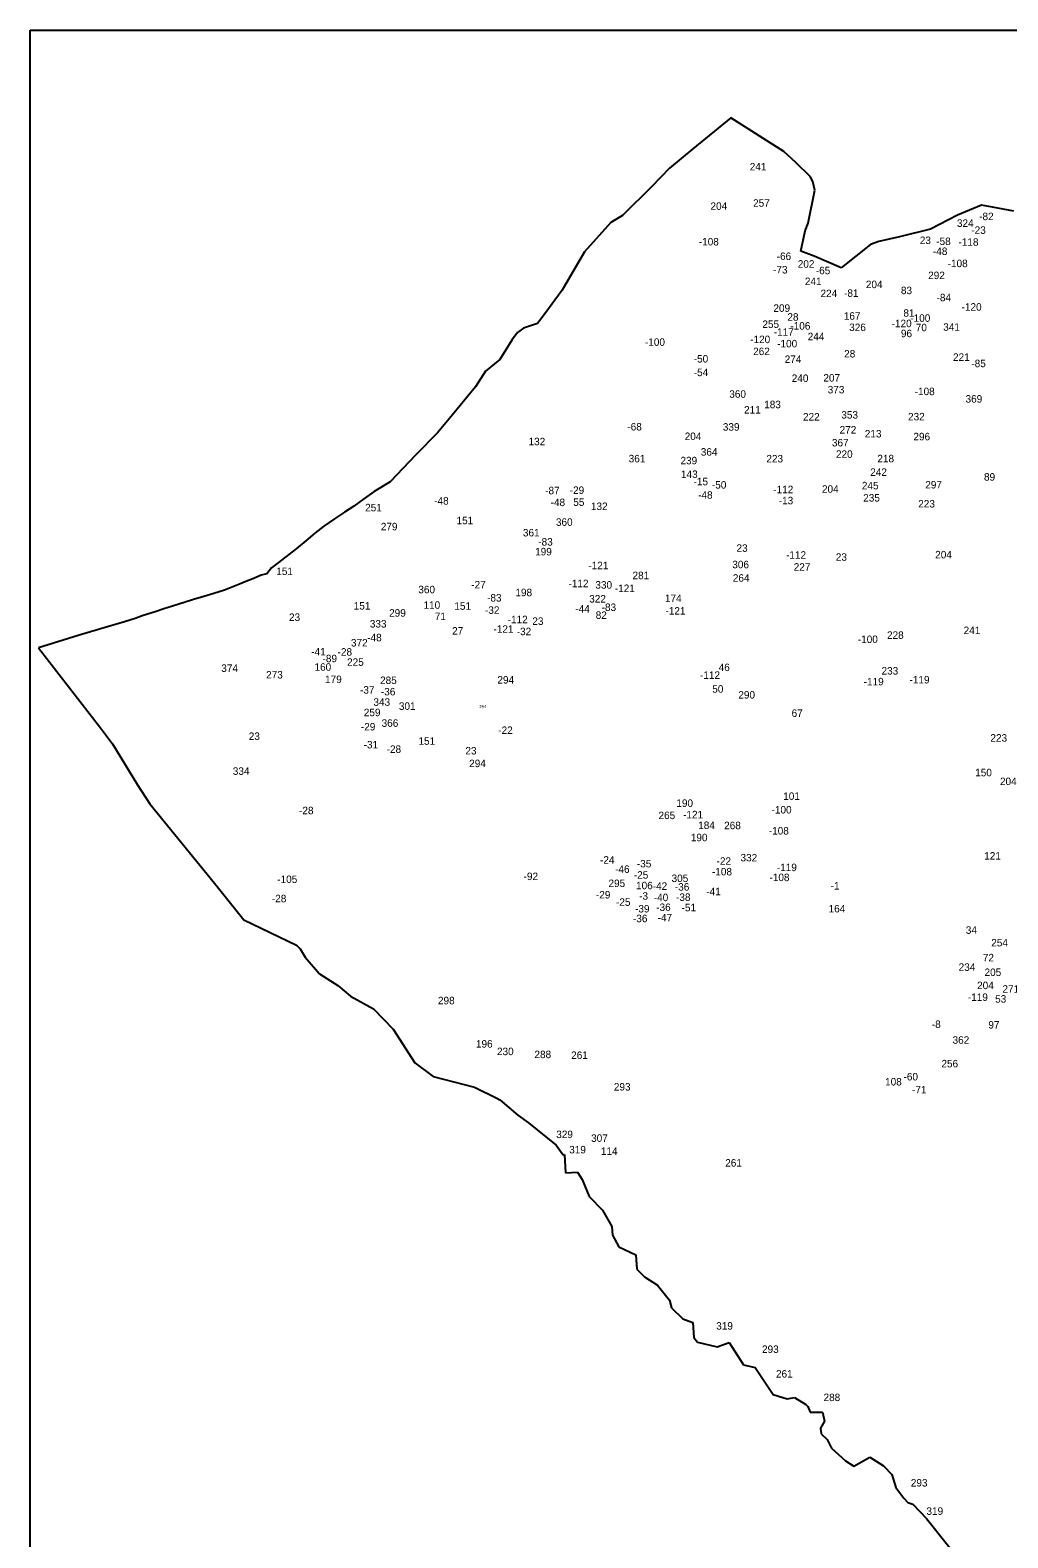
# Model space of a CAD drawing. Extents: x -780246 to -774760, y -968897 to -964868.
# Drawn here: x -780246 to -778940, y -966883 to -964868 of the extents above; entities that cross this region are included whole.
import ezdxf

# ---------------------------------------------------------------- set-up
doc = ezdxf.new("R2010")
doc.units = 0
for name, color, linetype in [('Vrstva 13', 7, 'Continuous'), ('Vrstva 15', 7, 'Continuous'), ('Vrstva 24', 7, 'Continuous')]:
    doc.layers.add(name, color=color, linetype=linetype)

msp = doc.modelspace()

# ---------------------------------------------------------------- linework, layer by layer
at = {"layer": 'Vrstva 13'}
for p, q in [((-779309.6, -964984.69), (-779360.72, -965026.33)), ((-779239.06, -965029.98), (-779309.6, -964984.69)), ((-779360.72, -965026.33), (-779391.82, -965051.9)), ((-779222.92, -965044.3), (-779239.06, -965029.98)), ((-779391.82, -965051.9), (-779415.48, -965076.37)), ((-779203.71, -965063.3), (-779222.92, -965044.3)), ((-779415.48, -965076.37), (-779454.7, -965115.52)), ((-779206.64, -965125.39), (-779197.51, -965081.63)), ((-779200.14, -965070.09), (-779203.71, -965063.3)), ((-779197.51, -965081.63), (-779200.14, -965070.09)), ((-778974.74, -965101.59), (-779006.8, -965114.81)), ((-778959.99, -965104.36), (-778974.74, -965101.59)), ((-779454.7, -965115.52), (-779470.03, -965124.73)), ((-779006.8, -965114.81), (-779042.87, -965133.8)), ((-778931.37, -965109.54), (-778959.99, -965104.36)), ((-779470.03, -965124.73), (-779505.59, -965163.81)), ((-779216.42, -965163.23), (-779210.44, -965135.91)), ((-779210.44, -965135.91), (-779206.64, -965125.39)), ((-779042.87, -965133.8), (-779084.41, -965143.66)), ((-779198.47, -965169.53), (-779216.42, -965163.23)), ((-779122.93, -965154.3), (-779162.25, -965185.45)), ((-779112.09, -965149.94), (-779122.93, -965154.3)), ((-779084.41, -965143.66), (-779112.09, -965149.94)), ((-779505.59, -965163.81), (-779535.39, -965215.38)), ((-779162.25, -965185.45), (-779198.47, -965169.53)), ((-779535.39, -965215.38), (-779558.32, -965246.72)), ((-779568.25, -965259.94), (-779586.8, -965266)), ((-779558.32, -965246.72), (-779568.25, -965259.94)), ((-779602.32, -965281.91), (-779618.53, -965307.85)), ((-779594.95, -965271.61), (-779602.32, -965281.91)), ((-779586.8, -965266), (-779594.95, -965271.61)), ((-779637.81, -965323.55), (-779651.1, -965344.66)), ((-779618.53, -965307.85), (-779637.81, -965323.55)), ((-779651.1, -965344.66), (-779681.99, -965382.06)), ((-779681.99, -965382.06), (-779702, -965406.17)), ((-779702, -965406.17), (-779730.91, -965435.25)), ((-779730.91, -965435.25), (-779765.15, -965471.56)), ((-779786.33, -965484.49), (-779800.42, -965494.27)), ((-779765.15, -965471.56), (-779786.33, -965484.49)), ((-779813.67, -965503.81), (-779826.27, -965512.25)), ((-779800.42, -965494.27), (-779813.67, -965503.81)), ((-779839.6, -965521.13), (-779853.98, -965530.67)), ((-779826.27, -965512.25), (-779839.6, -965521.13)), ((-779865.7, -965539.98), (-779877.93, -965550.2)), ((-779853.98, -965530.67), (-779865.7, -965539.98)), ((-779890.79, -965561.16), (-779900.47, -965568.61)), ((-779877.93, -965550.2), (-779890.79, -965561.16)), ((-779923.54, -965586.4), (-779929.9, -965594.58)), ((-779920.04, -965583.77), (-779923.54, -965586.4)), ((-779900.47, -965568.61), (-779920.04, -965583.77)), ((-779960.23, -965605.72), (-779964.43, -965607.62)), ((-779948.73, -965601.3), (-779960.23, -965605.72)), ((-779937.64, -965596.11), (-779948.73, -965601.3)), ((-779929.9, -965594.58), (-779937.64, -965596.11)), ((-780014.23, -965624.83), (-780028.14, -965628.88)), ((-780001.02, -965620.88), (-780014.23, -965624.83)), ((-779986.56, -965616.21), (-780001.02, -965620.88)), ((-779973.41, -965611.16), (-779986.56, -965616.21)), ((-779964.43, -965607.62), (-779973.41, -965611.16)), ((-780079.37, -965645.31), (-780095.14, -965650.36)), ((-780067.65, -965641.41), (-780079.37, -965645.31)), ((-780056.18, -965637.65), (-780067.65, -965641.41)), ((-780040.63, -965632.64), (-780056.18, -965637.65)), ((-780028.14, -965628.88), (-780040.63, -965632.64)), ((-780120.22, -965658.79), (-780153.64, -965668.51)), ((-780106.02, -965654.26), (-780120.22, -965658.79)), ((-780095.14, -965650.36), (-780106.02, -965654.26)), ((-780182.12, -965676.76), (-780235.06, -965693.49)), ((-780153.64, -965668.51), (-780182.12, -965676.76)), ((-780235.06, -965693.49), (-780152.24, -965800.3)), ((-780152.24, -965800.3), (-780136.47, -965821.92)), ((-780136.47, -965821.92), (-780102.87, -965876.42)), ((-780102.87, -965876.42), (-780086.5, -965901.85)), ((-780086.5, -965901.85), (-780042.98, -965955.26)), ((-780042.98, -965955.26), (-780000.03, -966007.94)), ((-780000.03, -966007.94), (-779960.89, -966057.03)), ((-779960.89, -966057.03), (-779890.2, -966090.93)), ((-779890.2, -966090.93), (-779885.23, -966095.76)), ((-779885.23, -966095.76), (-779878.73, -966107.09)), ((-779878.73, -966107.09), (-779859.38, -966129.51)), ((-779859.38, -966129.51), (-779835.21, -966144.93)), ((-779835.21, -966144.93), (-779818.04, -966159.18)), ((-779818.04, -966159.18), (-779787.3, -966176.21)), ((-779787.3, -966176.21), (-779761.3, -966203.24)), ((-779761.3, -966203.24), (-779732.23, -966248.32)), ((-779732.23, -966248.32), (-779707.81, -966266.62)), ((-779707.81, -966266.62), (-779652.48, -966280.84)), ((-779652.48, -966280.84), (-779622.47, -966295.41)), ((-779622.47, -966295.41), (-779618.41, -966297.63)), ((-779618.41, -966297.63), (-779594.6, -966318.31)), ((-779594.6, -966318.31), (-779580.07, -966328.54)), ((-779580.07, -966328.54), (-779543.08, -966358.28)), ((-779543.08, -966358.28), (-779534.09, -966371.21)), ((-779534.09, -966371.21), (-779532.11, -966370.7)), ((-779532.11, -966370.7), (-779530.87, -966395.46)), ((-779530.87, -966395.46), (-779514.66, -966394.59)), ((-779514.66, -966394.59), (-779508.52, -966404.45)), ((-779508.52, -966404.45), (-779499.02, -966426.88)), ((-779499.02, -966426.88), (-779481.49, -966445.22)), ((-779481.49, -966445.22), (-779468.78, -966467.14)), ((-779468.78, -966467.14), (-779467.76, -966478.72)), ((-779467.76, -966478.72), (-779459.43, -966494.18)), ((-779459.43, -966494.18), (-779436.64, -966505.14)), ((-779436.64, -966505.14), (-779435.25, -966524.35)), ((-779435.25, -966524.35), (-779425.39, -966534.65)), ((-779425.39, -966534.65), (-779407.86, -966545.68)), ((-779407.86, -966545.68), (-779391.64, -966565.85)), ((-779391.64, -966565.85), (-779389.3, -966575.94)), ((-779389.3, -966575.94), (-779373.96, -966590.48)), ((-779373.96, -966590.48), (-779360.74, -966595.37)), ((-779360.74, -966595.37), (-779359.28, -966615.68)), ((-779359.28, -966615.68), (-779354.31, -966621.67)), ((-779354.31, -966621.67), (-779327.87, -966628.1)), ((-779327.87, -966628.1), (-779312.09, -966622.11)), ((-779312.09, -966622.11), (-779292.96, -966652.07)), ((-779292.96, -966652.07), (-779277.47, -966655.72)), ((-779277.47, -966655.72), (-779253.37, -966692.03)), ((-779253.37, -966692.03), (-779234.31, -966697.51)), ((-779234.31, -966697.51), (-779224.88, -966695.61)), ((-779224.88, -966695.61), (-779209.4, -966705.12)), ((-779209.4, -966705.12), (-779206.99, -966707.82)), ((-779206.99, -966707.82), (-779203.93, -966715.42)), ((-779203.93, -966715.42), (-779187.35, -966715.42)), ((-779187.35, -966715.42), (-779184.5, -966727.62)), ((-779184.5, -966727.62), (-779190.11, -966736.83)), ((-779190.11, -966736.83), (-779188.95, -966744.43)), ((-779188.95, -966744.43), (-779181.2, -966751.96)), ((-779181.2, -966751.96), (-779175.29, -966763.5)), ((-779175.29, -966763.5), (-779156.74, -966780.38)), ((-779145.24, -966787.65), (-779124.16, -966775.64)), ((-779124.16, -966775.64), (-779105.9, -966787.25)), ((-779156.74, -966780.38), (-779145.24, -966787.65)), ((-779105.9, -966787.25), (-779094.51, -966798.72)), ((-779094.51, -966798.72), (-779089.47, -966816.26)), ((-779089.47, -966816.26), (-779078.66, -966830.58)), ((-779078.66, -966830.58), (-779073.4, -966836.35)), ((-779073.4, -966836.35), (-779066.46, -966838.32)), ((-779066.46, -966838.32), (-779048.33, -966857.77)), ((-779048.33, -966857.77), (-778991.94, -966927.92))]:
    msp.add_line(p, q, dxfattribs=at)
msp.add_lwpolyline([(-780246.31, -964867.52), (-774759.73, -964867.52), (-774759.73, -968897.03), (-780246.31, -968897.03)], close=True, dxfattribs=at)

# ---------------------------------------------------------------- texts
at = {"layer": 'Vrstva 15'}
for s, p in [('241', (-779284.526, -965055.07)), ('204', (-779336.962, -965107.75)), ('257', (-779280.066, -965103.64)), ('324', (-779007.582, -965130.54)), ('-82', (-778977.84, -965121.56)), ('23', (-779057.206, -965153.52)), ('-23', (-778988.35, -965139.85)), ('-108', (-779352.574, -965155.41)), ('-48', (-779039.686, -965168.2)), ('-58', (-779035.21, -965154.87)), ('-118', (-779005.529, -965155.79)), ('-73', (-779253.358, -965192.9)), ('-66', (-779248.487, -965174.84)), ('202', (-779220.326, -965185.12)), ('-65', (-779196.204, -965193.91)), ('-108', (-779019.984, -965184.43)), ('241', (-779210.816, -965208.42)), ('204', (-779129.312, -965212.49)), ('292', (-779046.03, -965200.37)), ('224', (-779189.892, -965224.49)), ('-81', (-779158.454, -965224.11)), ('83', (-779082.456, -965220.52)), ('-84', (-779034.796, -965230.02)), ('209', (-779252.87, -965244.17)), ('81', (-779079.141, -965250.7)), ('-120', (-779001.335, -965242.61)), ('255', (-779267.626, -965265.69)), ('28', (-779234.196, -965256.01)), ('-106', (-779230.228, -965267.97)), ('167', (-779158.833, -965254.65)), ('326', (-779151.59, -965269.87)), ('-120', (-779094.845, -965264.7)), ('-100', (-779069.914, -965257.52)), ('70', (-779062.605, -965270.08)), ('341', (-779025.906, -965269.46)), ('-100', (-779424.584, -965289.6)), ('-120', (-779283.925, -965286.02)), ('-117', (-779252.408, -965276.19)), ('-100', (-779247.854, -965291.66)), ('244', (-779207.038, -965282.13)), ('96', (-779082.444, -965278.07)), ('-50', (-779359.36, -965312)), ('262', (-779280, -965301.99)), ('274', (-779237.821, -965312.47)), ('28', (-779158.326, -965305.17)), ('221', (-779012.861, -965309.73)), ('-54', (-779359.346, -965330.16)), ('-85', (-778988.31, -965318.2)), ('240', (-779228.382, -965337.92)), ('207', (-779186.135, -965337.42)), ('373', (-779180.325, -965353.23)), ('360', (-779311.86, -965359.07)), ('183', (-779265.221, -965373.04)), ('-108', (-779064.034, -965355.56)), ('369', (-778996.074, -965365.56)), ('211', (-779292.076, -965380.14)), ('222', (-779213.336, -965389.51)), ('353', (-779162.116, -965386.87)), ('232', (-779072.946, -965389.31)), ('-68', (-779448.104, -965402.81)), ('204', (-779371.472, -965415.55)), ('339', (-779320.46, -965403.04)), ('272', (-779164.395, -965406.88)), ('213', (-779130.741, -965412.14)), ('132', (-779580.171, -965422.56)), ('367', (-779174.688, -965424.13)), ('296', (-779065.744, -965415.95)), ('361', (-779446.354, -965445.39)), ('239', (-779377.1, -965448.02)), ('364', (-779349.966, -965436.45)), ('223', (-779262.316, -965445.51)), ('220', (-779169.286, -965439.36)), ('218', (-779113.921, -965445.35)), ('143', (-779376.426, -965466.32)), ('242', (-779123.482, -965463.49)), ('89', (-778971.41, -965469.86)), ('-87', (-779557.919, -965488.13)), ('-29', (-779525.134, -965487.62)), ('-15', (-779359.644, -965476.03)), ('-48', (-779353.486, -965494.06)), ('-50', (-779335.07, -965480.52)), ('-112', (-779253.109, -965486.68)), ('204', (-779187.972, -965486.06)), ('245', (-779134.592, -965481.49)), ('297', (-779049.928, -965480.34)), ('251', (-779798.591, -965510.9)), ('-48', (-779706.296, -965501.9)), ('-48', (-779550.646, -965503.95)), ('55', (-779520.386, -965503.6)), ('132', (-779496.841, -965509.15)), ('-13', (-779245.724, -965501.47)), ('235', (-779132.846, -965497.84)), ('223', (-779059.336, -965505.78)), ('279', (-779777.668, -965536.29)), ('151', (-779676.436, -965528.16)), ('360', (-779543.59, -965530.27)), ('361', (-779587.714, -965544.47)), ('-83', (-779567.17, -965556.69)), ('199', (-779571.378, -965569.8)), ('23', (-779302.216, -965565.02)), ('-112', (-779235.969, -965574.23)), ('204', (-779036.612, -965573.84)), ('151', (-779917.396, -965596.04)), ('-121', (-779500.269, -965588.33)), ('306', (-779307.86, -965587.02)), ('227', (-779225.766, -965590.3)), ('23', (-779169.476, -965577.01)), ('-27', (-779656.719, -965613.99)), ('-112', (-779526.779, -965612.35)), ('330', (-779490.846, -965614.27)), ('281', (-779441.191, -965601.62)), ('264', (-779307.126, -965605.01)), ('360', (-779727.5, -965620.46)), ('-83', (-779635.61, -965631.54)), ('198', (-779597.714, -965624.38)), ('322', (-779499.076, -965632.85)), ('-121', (-779464.839, -965618.8)), ('174', (-779397.886, -965632.2)), ('23', (-779900.356, -965657.47)), ('151', (-779813.876, -965642.26)), ('299', (-779766.534, -965651.79)), ('110', (-779720.546, -965641.22)), ('71', (-779705.51, -965656.43)), ('151', (-779679.356, -965642.55)), ('-32', (-779638.39, -965647.96)), ('-44', (-779517.652, -965646.34)), ('82', (-779490.386, -965654.72)), ('-83', (-779482.46, -965644.15)), ('-121', (-779397.179, -965648.97)), ('333', (-779792.316, -965666.29)), ('27', (-779682.336, -965675.79)), ('-121', (-779627.059, -965673.29)), ('-112', (-779608.059, -965660.56)), ('-32', (-779595.92, -965676.51)), ('23', (-779575.096, -965662.76)), ('241', (-778998.626, -965675)), ('372', (-779817.535, -965691.62)), ('-48', (-779795.826, -965684.7)), ('-100', (-779140.064, -965686.99)), ('228', (-779101.046, -965681.45)), ('-41', (-779870.64, -965703.61)), ('-89', (-779855.504, -965712.68)), ('-28', (-779835.39, -965703.89)), ('225', (-779822.726, -965717.49)), ('374', (-779990.861, -965725.63)), ('273', (-779930.905, -965734.41)), ('160', (-779866.274, -965724.02)), ('-112', (-779350.969, -965734.92)), ('46', (-779326.026, -965724.55)), ('233', (-779108.366, -965729.15)), ('179', (-779852.173, -965740.55)), ('-37', (-779805.449, -965754.7)), ('285', (-779778.626, -965741.83)), ('-36', (-779777.504, -965757.04)), ('294', (-779621.796, -965741.18)), ('50', (-779334.616, -965753.37)), ('-119', (-779132.183, -965743.55)), ('-119', (-779070.953, -965741.06)), ('343', (-779787.522, -965770.93)), ('301', (-779753.48, -965776.35)), ('290', (-779299.76, -965761.27)), ('259', (-779800.36, -965784.83)), ('67', (-779228.548, -965785.72)), ('23', (-779954.156, -965816.59)), ('-29', (-779804.274, -965803.9)), ('366', (-779776.564, -965799.03)), ('-22', (-779620.67, -965808.59)), ('223', (-778962.806, -965818.87)), ('-31', (-779800.594, -965827.92)), ('-28', (-779769.82, -965833.92)), ('151', (-779727.316, -965823.05)), ('23', (-779664.586, -965836.02)), ('294', (-779659.536, -965852.97)), ('334', (-779975.472, -965863.24)), ('150', (-778983.211, -965865.17)), ('204', (-778950.042, -965876.95)), ('101', (-779239.805, -965896.75)), ('-28', (-779886.91, -965915.93)), ('190', (-779382.624, -965906.11)), ('-100', (-779255.334, -965914.97)), ('265', (-779406.47, -965922.49)), ('-121', (-779373.639, -965921.4)), ('184', (-779353.437, -965935.67)), ('268', (-779318.73, -965935.95)), ('190', (-779363.314, -965952.05)), ('-108', (-779259.034, -965943.1)), ('332', (-779296.846, -965978.99)), ('121', (-778971.146, -965976.63)), ('-24', (-779484.656, -965982.06)), ('-46', (-779464.51, -965994.36)), ('-35', (-779435.35, -965987.02)), ('-108', (-779334.994, -965997.73)), ('-22', (-779328.82, -965983.53)), ('-119', (-779248.313, -965992.03)), ('-105', (-779916.054, -966007.87)), ('-92', (-779586.774, -966003.98)), ('295', (-779473.34, -966013.31)), ('-25', (-779439.46, -966002.09)), ('106', (-779436.464, -966016.23)), ('-42', (-779414.186, -966017.03)), ('305', (-779388.986, -966006.57)), ('-36', (-779384.584, -966018.05)), ('-108', (-779258.154, -966005.38)), ('-1', (-779176.294, -966016.58)), ('-28', (-779923.22, -966033.65)), ('-29', (-779490.124, -966028.59)), ('-25', (-779463.28, -966038.4)), ('-3', (-779432.36, -966030.23)), ('-40', (-779412.766, -966032.19)), ('-38', (-779383.06, -966031.82)), ('-41', (-779342.7, -966024.25)), ('-36', (-779440.584, -966060.31)), ('-39', (-779437.804, -966047.27)), ('-36', (-779409.534, -966045.28)), ('-47', (-779407.554, -966059.19)), ('-51', (-779375.624, -966045.73)), ('164', (-779179.1, -966047.24)), ('34', (-778995.702, -966075.82)), ('254', (-778961.732, -966092.69)), ('72', (-778972.945, -966112.63)), ('234', (-779005.312, -966125.32)), ('205', (-778970.676, -966132.2)), ('204', (-778980.622, -966149.83)), ('271', (-778946.71, -966154.56)), ('298', (-779701.28, -966170.05)), ('-119', (-778992.993, -966165.58)), ('53', (-778956.556, -966167.87)), ('-8', (-779041.12, -966201.72)), ('97', (-778965.598, -966202.47)), ('196', (-779650.468, -966228)), ('230', (-779622.356, -966238.08)), ('288', (-779572.276, -966242.07)), ('362', (-779013.45, -966222.82)), ('261', (-779523.224, -966243.14)), ('256', (-779028.3, -966254.39)), ('108', (-779103.61, -966278.64)), ('-60', (-779078.944, -966271.9)), ('293', (-779466.14, -966285.39)), ('-71', (-779067.573, -966289.34)), ('329', (-779543.14, -966348.98)), ('307', (-779496.525, -966354.01)), ('319', (-779525.844, -966369.39)), ('114', (-779483.502, -966371.42)), ('261', (-779317.314, -966387.1)), ('319', (-779329.344, -966605.08)), ('293', (-779268.13, -966636.25)), ('261', (-779249.464, -966669.18)), ('288', (-779185.866, -966700.63)), ('293', (-779069.21, -966814.87)), ('319', (-779048.344, -966852.74))]:
    msp.add_text(s, height=10, dxfattribs=at).set_placement(p)
at = {"layer": 'Vrstva 24'}
msp.add_text('294', height=4, dxfattribs=at).set_placement((-779645.978, -965774.08))

doc.saveas('drawing.dxf')
